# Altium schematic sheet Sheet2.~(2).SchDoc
size A; SheetNumber: 1; SheetTotal: 1
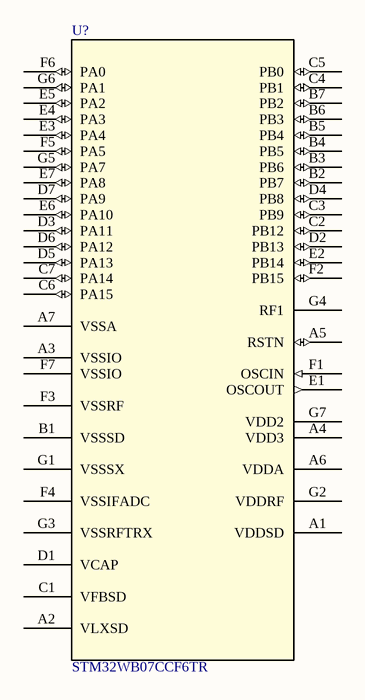
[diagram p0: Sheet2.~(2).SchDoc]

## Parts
U?  STM32WB07CCF6TR  [WLCSP49_7P140X3P140_STM]

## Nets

Not connected (* = marked no-connect by the designer): U? A1(VDDSD) A2(VLXSD) A3(VSSIO) A4(VDD3) A5(RSTN) A6(VDDA) A7(VSSA) B1(VSSSD) B2(PB7) B3(PB6) B4(PB5) B5(PB4) B6(PB3) B7(PB2) C1(VFBSD) C2(PB12) C3(PB9) C4(PB1) C5(PB0) C6(PA15) C7(PA14) D1(VCAP) D2(PB13) D3(PA11) D4(PB8) D5(PA13) D6(PA12) D7(PA9) E1(OSCOUT) E2(PB14) E3(PA4) E4(PA3) E5(PA2) E6(PA10) E7(PA8) F1(OSCIN) F2(PB15) F3(VSSRF) F4(VSSIFADC) F5(PA5) F6(PA0) F7(VSSIO) G1(VSSSX) G2(VDDRF) G3(VSSRFTRX) G4(RF1) G5(PA7) G6(PA1) G7(VDD2)

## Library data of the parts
U? = STM32WB07CCF6TR: Ultra-low-power, Arm Cortex-M0+ MCU 64 MHz with 256 Kbytes of Flash memory, 64 Kbytes of RAM,  Bluetooth LE 5.4; Manufacturer_Name: STMicroelectronics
